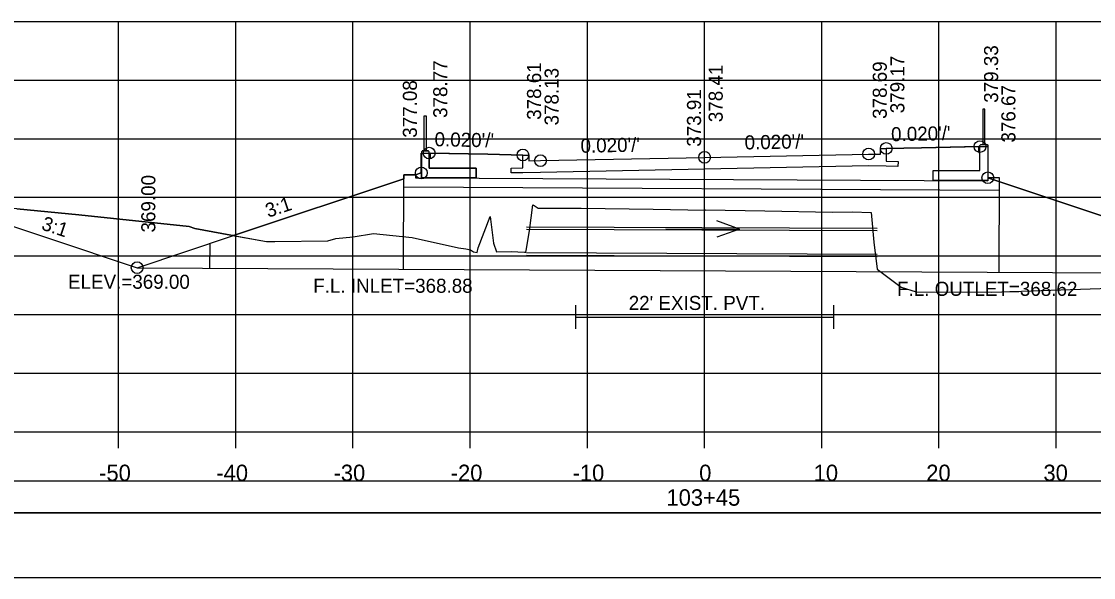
# Model space of a CAD drawing. Extents: x -37291014 to -37290680, y -936053 to -933067.
# Drawn here: x -37290901.4 to -37290809.9, y -935351.7 to -935304.3 of the extents above; entities that cross this region are included whole.
import ezdxf

# ---------------------------------------------------------------- set-up
doc = ezdxf.new("R2010")
doc.units = 0
for name, color, linetype in [('Default', 7, 'Continuous'), ('R_Alt Surface', 7, 'Continuous'), ('R_Axis', 7, 'Continuous'), ('R_Axis Annot', 7, 'Continuous'), ('R_Contours', 7, 'Continuous'), ('R_Exist Surface', 7, 'Continuous'), ('R_Fin Surface', 7, 'Continuous'), ('R_Grid', 7, 'Continuous'), ('R_No Plot', 7, 'Continuous'), ('R_Water', 7, 'Continuous'), ('R_Water Annot', 7, 'Continuous'), ('R_Xsect Elev', 7, 'Continuous'), ('R_Xsect Slope', 7, 'Continuous')]:
    doc.layers.add(name, color=color, linetype=linetype)

msp = doc.modelspace()

# ---------------------------------------------------------------- linework, layer by layer
at = {"layer": 'Default'}
for p, q in [((-37290867.018, -935315.353), (-37290867.018, -935312.353)), ((-37290867.018, -935312.353), (-37290866.852, -935312.353)), ((-37290866.852, -935312.353), (-37290866.852, -935315.353)), ((-37290819.352, -935311.793), (-37290819.352, -935314.793)), ((-37290819.185, -935311.793), (-37290819.352, -935311.793)), ((-37290819.185, -935314.793), (-37290819.185, -935311.793)), ((-37290819.602, -935314.876), (-37290819.539, -935314.814)), ((-37290819.602, -935317.034), (-37290819.602, -935314.876)), ((-37290819.539, -935314.793), (-37290818.997, -935314.793)), ((-37290819.539, -935314.814), (-37290819.539, -935314.793)), ((-37290819.539, -935314.814), (-37290818.997, -935314.814)), ((-37290818.997, -935314.793), (-37290818.997, -935314.814)), ((-37290818.997, -935314.814), (-37290818.935, -935314.876)), ((-37290818.935, -935314.876), (-37290818.935, -935317.868)), ((-37290867.206, -935315.374), (-37290867.268, -935315.436)), ((-37290867.268, -935315.436), (-37290867.268, -935317.643)), ((-37290866.664, -935315.353), (-37290867.206, -935315.353)), ((-37290867.206, -935315.353), (-37290867.206, -935315.374)), ((-37290866.664, -935315.374), (-37290867.206, -935315.374)), ((-37290866.664, -935315.374), (-37290866.664, -935315.353)), ((-37290866.602, -935315.436), (-37290866.664, -935315.374)), ((-37290866.602, -935316.81), (-37290866.602, -935315.436)), ((-37290862.598, -935316.81), (-37290866.602, -935316.81)), ((-37290862.598, -935317.643), (-37290862.598, -935316.81)), ((-37290862.598, -935317.643), (-37290867.268, -935317.643)), ((-37290823.605, -935317.868), (-37290823.605, -935317.034)), ((-37290823.605, -935317.034), (-37290819.602, -935317.034)), ((-37290823.605, -935317.868), (-37290818.935, -935317.868))]:
    msp.add_line(p, q, dxfattribs=at)
for points in [[(-37290819.685, -935315.48), (-37290819.602, -935315.48), (-37290819.602, -935314.98), (-37290819.685, -935314.98), (-37290819.685, -935315.48)], [(-37290866.518, -935316.04), (-37290866.602, -935316.04), (-37290866.602, -935315.54), (-37290866.518, -935315.54), (-37290866.518, -935316.04)]]:
    msp.add_lwpolyline(points, dxfattribs=at)
for points in [[(-37290992.481, -935346.216), (-37290693.722, -935346.216), (-37290693.722, -935343.51), (-37290992.481, -935343.51)], [(-37290992.481, -935351.738), (-37290693.722, -935351.738), (-37290693.722, -935346.216), (-37290992.481, -935346.216)]]:
    msp.add_lwpolyline(points, close=True, dxfattribs=at)
at = {"layer": 'R_Alt Surface'}
for points in [[(-37290827.602, -935315.14), (-37290827.602, -935316.233), (-37290826.592, -935316.254), (-37290826.602, -935316.67), (-37290827.602, -935316.65), (-37290829.102, -935316.62), (-37290843.102, -935316.9), (-37290857.102, -935317.18), (-37290858.602, -935317.21), (-37290859.602, -935317.23), (-37290859.612, -935316.814), (-37290858.602, -935316.793), (-37290858.602, -935315.7)], [(-37290854.102, -935328.517), (-37290854.102, -935330.517)], [(-37290832.102, -935328.517), (-37290832.102, -935330.517)], [(-37290854.102, -935329.517), (-37290832.102, -935329.517)]]:
    msp.add_lwpolyline(points, dxfattribs=at)
at = {"layer": 'R_Axis'}
for p, q in [((-37290993.102, -935339.31), (-37290693.102, -935339.31)), ((-37290893.102, -935340.71), (-37290893.102, -935339.31)), ((-37290883.102, -935340.71), (-37290883.102, -935339.31)), ((-37290873.102, -935340.71), (-37290873.102, -935339.31)), ((-37290863.102, -935340.71), (-37290863.102, -935339.31)), ((-37290853.102, -935340.71), (-37290853.102, -935339.31)), ((-37290843.102, -935340.71), (-37290843.102, -935339.31)), ((-37290833.102, -935340.71), (-37290833.102, -935339.31)), ((-37290823.102, -935340.71), (-37290823.102, -935339.31)), ((-37290813.102, -935340.71), (-37290813.102, -935339.31))]:
    msp.add_line(p, q, dxfattribs=at)
at = {"layer": 'R_Contours'}
for p, q in [((-37290819.602, -935317.034), (-37290819.602, -935315.48)), ((-37290866.602, -935316.04), (-37290866.602, -935316.81)), ((-37290866.602, -935316.81), (-37290862.598, -935316.81)), ((-37290862.598, -935316.81), (-37290862.598, -935317.643)), ((-37290867.268, -935317.643), (-37290867.268, -935317.23)), ((-37290862.598, -935317.643), (-37290867.268, -935317.643)), ((-37290823.605, -935317.868), (-37290823.605, -935317.034)), ((-37290823.605, -935317.034), (-37290819.602, -935317.034)), ((-37290818.935, -935317.64), (-37290818.935, -935317.868)), ((-37290818.935, -935317.868), (-37290823.605, -935317.868)), ((-37290883.304, -935322.573), (-37290883.537, -935322.531))]:
    msp.add_line(p, q, dxfattribs=at)
for points in [[(-37290819.685, -935314.982), (-37290824.602, -935315.08), (-37290827.602, -935315.14)], [(-37290819.602, -935315.48), (-37290819.685, -935315.48), (-37290819.685, -935314.982)], [(-37290866.518, -935315.542), (-37290866.518, -935316.04), (-37290866.602, -935316.04)], [(-37290858.602, -935315.7), (-37290861.602, -935315.64), (-37290866.518, -935315.542)], [(-37290827.602, -935315.14), (-37290827.602, -935316.233), (-37290826.592, -935316.254), (-37290826.602, -935316.67), (-37290827.602, -935316.65), (-37290829.102, -935316.62), (-37290843.102, -935316.9), (-37290857.102, -935317.18), (-37290858.602, -935317.21), (-37290859.602, -935317.23), (-37290859.612, -935316.814), (-37290858.602, -935316.793), (-37290858.602, -935315.7)], [(-37290867.273, -935317.23), (-37290867.762, -935317.393), (-37290868.762, -935317.385), (-37290868.763, -935317.727), (-37290883.304, -935322.573)], [(-37290867.268, -935317.23), (-37290867.273, -935317.23)], [(-37290818.931, -935317.64), (-37290818.935, -935317.64)], [(-37290792.881, -935326.322), (-37290795.774, -935325.358), (-37290818.931, -935317.64)], [(-37290883.537, -935322.531), (-37290886.603, -935321.977), (-37290887.068, -935321.808), (-37290896.495, -935320.808), (-37290901.786, -935320.281), (-37290906.76, -935320.229)], [(-37290906.76, -935320.229), (-37290891.515, -935325.31), (-37290883.304, -935322.573)], [(-37290883.304, -935322.573), (-37290880.471, -935323.085), (-37290879.756, -935323.065), (-37290875.249, -935323.015), (-37290874.553, -935322.828), (-37290873.089, -935322.671), (-37290871.345, -935322.391), (-37290868.054, -935322.737), (-37290864.09, -935323.608), (-37290863.469, -935323.712), (-37290863.063, -935323.792), (-37290862.824, -935323.961), (-37290862.505, -935324.025), (-37290862.424, -935323.631), (-37290861.394, -935320.942), (-37290861.097, -935323.212), (-37290860.858, -935323.964), (-37290859.59, -935323.925), (-37290858.466, -935323.982), (-37290858.346, -935323.986), (-37290858.328, -935323.836), (-37290858.045, -935322.171), (-37290857.763, -935319.937), (-37290857.65, -935320.015), (-37290857.302, -935320.24), (-37290856.619, -935320.246), (-37290853.626, -935320.229), (-37290847.481, -935320.323), (-37290843.054, -935320.401), (-37290843.023, -935320.385), (-37290837.955, -935320.461), (-37290832.174, -935320.572), (-37290830.517, -935320.553), (-37290828.897, -935320.598), (-37290828.662, -935323.123), (-37290828.379, -935325.431), (-37290826.325, -935326.98), (-37290825.034, -935327.371), (-37290818.601, -935327.388), (-37290805.994, -935326.984)]]:
    msp.add_lwpolyline(points, dxfattribs=at)
at = {"layer": 'R_Exist Surface'}
msp.add_lwpolyline([(-37290901.786, -935320.281), (-37290896.495, -935320.808), (-37290887.068, -935321.808), (-37290886.603, -935321.977), (-37290883.537, -935322.531), (-37290880.471, -935323.085), (-37290879.756, -935323.065), (-37290875.249, -935323.015), (-37290874.553, -935322.828), (-37290873.089, -935322.671), (-37290871.345, -935322.391), (-37290868.054, -935322.737), (-37290864.09, -935323.608), (-37290863.469, -935323.712), (-37290863.063, -935323.792), (-37290862.824, -935323.961), (-37290862.505, -935324.025), (-37290862.424, -935323.631), (-37290861.394, -935320.942), (-37290861.097, -935323.212), (-37290860.858, -935323.964), (-37290859.59, -935323.925), (-37290858.466, -935323.982), (-37290858.346, -935323.986), (-37290858.328, -935323.836), (-37290858.045, -935322.171), (-37290857.763, -935319.937), (-37290857.65, -935320.015), (-37290857.302, -935320.24), (-37290856.619, -935320.246), (-37290853.626, -935320.229), (-37290847.481, -935320.323), (-37290843.054, -935320.401), (-37290843.023, -935320.385), (-37290837.955, -935320.461), (-37290832.174, -935320.572), (-37290830.517, -935320.553), (-37290828.897, -935320.598), (-37290828.662, -935323.123), (-37290828.379, -935325.431), (-37290826.325, -935326.98), (-37290825.034, -935327.371), (-37290818.601, -935327.388), (-37290805.994, -935326.984)], dxfattribs=at)
at = {"layer": 'R_Fin Surface'}
msp.add_lwpolyline([(-37290906.76, -935320.229), (-37290891.515, -935325.31), (-37290883.304, -935322.573), (-37290868.763, -935317.727), (-37290868.762, -935317.385), (-37290867.762, -935317.393), (-37290867.273, -935317.23), (-37290867.272, -935315.54), (-37290866.602, -935315.54), (-37290861.602, -935315.64), (-37290858.602, -935315.7), (-37290858.102, -935315.7), (-37290858.101, -935316.2), (-37290857.102, -935316.18), (-37290843.102, -935315.9), (-37290829.102, -935315.62), (-37290828.103, -935315.64), (-37290828.102, -935315.14), (-37290827.602, -935315.14), (-37290824.602, -935315.08), (-37290819.602, -935314.98), (-37290818.932, -935314.98), (-37290818.931, -935317.64), (-37290795.774, -935325.358)], dxfattribs=at)
at = {"layer": 'R_Grid'}
for p, q in [((-37290993.102, -935304.31), (-37290693.102, -935304.31)), ((-37290893.102, -935339.31), (-37290893.102, -935304.31)), ((-37290883.102, -935339.31), (-37290883.102, -935304.31)), ((-37290873.102, -935339.31), (-37290873.102, -935304.31)), ((-37290863.102, -935339.31), (-37290863.102, -935304.31)), ((-37290853.102, -935339.31), (-37290853.102, -935304.31)), ((-37290843.102, -935339.31), (-37290843.102, -935304.31)), ((-37290833.102, -935339.31), (-37290833.102, -935304.31)), ((-37290823.102, -935339.31), (-37290823.102, -935304.31)), ((-37290813.102, -935339.31), (-37290813.102, -935304.31)), ((-37290993.102, -935309.31), (-37290693.102, -935309.31)), ((-37290993.102, -935314.31), (-37290693.102, -935314.31)), ((-37290993.102, -935319.31), (-37290693.102, -935319.31)), ((-37290993.102, -935324.31), (-37290693.102, -935324.31)), ((-37290993.102, -935329.31), (-37290693.102, -935329.31)), ((-37290993.102, -935334.31), (-37290693.102, -935334.31)), ((-37290993.102, -935339.31), (-37290693.102, -935339.31))]:
    msp.add_line(p, q, dxfattribs=at)
at = {"layer": 'R_No Plot'}
for p, q in [((-37290858.295, -935321.813), (-37290828.372, -935321.935)), ((-37290858.295, -935324.23), (-37290828.372, -935324.352))]:
    msp.add_line(p, q, dxfattribs=at)
for centre in [(-37290866.602, -935315.54), (-37290827.602, -935315.14), (-37290819.602, -935314.98), (-37290858.602, -935315.7), (-37290857.102, -935316.18), (-37290843.102, -935315.9), (-37290829.102, -935315.62), (-37290829.102, -935315.62), (-37290867.273, -935317.23), (-37290818.931, -935317.64), (-37290891.515, -935325.31)]:
    msp.add_circle(centre, 0.5, dxfattribs=at)
at = {"layer": 'R_Water'}
for p, q in [((-37290868.803, -935325.427), (-37290868.762, -935317.385)), ((-37290868.762, -935317.385), (-37290867.762, -935317.39)), ((-37290867.762, -935317.39), (-37290867.763, -935317.64)), ((-37290867.763, -935317.64), (-37290818.932, -935317.892)), ((-37290818.93, -935317.642), (-37290818.932, -935317.892)), ((-37290817.93, -935317.647), (-37290818.93, -935317.642)), ((-37290817.972, -935325.688), (-37290817.93, -935317.647)), ((-37290868.767, -935318.427), (-37290817.936, -935318.689)), ((-37290858.295, -935322.022), (-37290828.372, -935322.144)), ((-37290885.303, -935325.342), (-37290885.292, -935323.234)), ((-37290858.295, -935324.022), (-37290828.372, -935324.144)), ((-37290891.525, -935325.31), (-37290794.412, -935325.81))]:
    msp.add_line(p, q, dxfattribs=at)
at = {"layer": 'R_Water Annot'}
for p, q in [((-37290840.125, -935322.026), (-37290842.046, -935321.318)), ((-37290846.41, -935322.001), (-37290840.125, -935322.026)), ((-37290840.125, -935322.026), (-37290842.051, -935322.719))]:
    msp.add_line(p, q, dxfattribs=at)
at = {"layer": 'R_Xsect Elev'}
msp.add_line((-37290843.102, -935320.4), (-37290843.102, -935307.995), dxfattribs=at)

# ---------------------------------------------------------------- texts
at = {"layer": 'R_Axis Annot'}
for s, p in [('-50', (-37290894.761, -935343.51)), ('-40', (-37290884.761, -935343.51)), ('-30', (-37290874.761, -935343.51)), ('-20', (-37290864.761, -935343.51)), ('-10', (-37290854.364, -935343.51)), ('0', (-37290843.559, -935343.51)), ('10', (-37290833.791, -935343.51)), ('20', (-37290824.187, -935343.51)), ('30', (-37290814.187, -935343.51)), ('103+45', (-37290846.354, -935345.61))]:
    msp.add_text(s, height=1.4, dxfattribs=at).set_placement(p)
at = {"layer": 'R_Water'}
msp.add_text("22' EXIST. PVT.", height=1.2, dxfattribs=at).set_placement((-37290849.575, -935328.917))
at = {"layer": 'R_Water Annot'}
for s, p in [('F.L. INLET=368.88', (-37290876.494, -935327.451)), ('F.L. OUTLET=368.62', (-37290826.674, -935327.713))]:
    msp.add_text(s, height=1.2, dxfattribs=at).set_placement(p)
at = {"layer": 'R_Xsect Elev'}
for s, p in [('379.33', (-37290818.052, -935311.246)), ('378.77', (-37290865.052, -935312.54)), ('379.17', (-37290826.052, -935312.14)), ('378.61', (-37290857.052, -935312.7)), ('378.13', (-37290855.552, -935313.18)), ('378.41', (-37290841.552, -935312.9)), ('378.69', (-37290827.552, -935312.62)), ('377.08', (-37290867.646, -935314.23)), ('373.91', (-37290843.402, -935314.995)), ('376.67', (-37290816.578, -935314.64)), ('369.00', (-37290889.965, -935322.31))]:
    msp.add_text(s, height=1.2, rotation=90, dxfattribs=at).set_placement(p)
msp.add_text('ELEV.=369.00', height=1.2, dxfattribs=at).set_placement((-37290897.416, -935327.11))
at = {"layer": 'R_Xsect Slope'}
for s, rotation, p in [("0.020'/'", 1.14576, (-37290827.175, -935314.532)), ("0.020'/'", 358.85424, (-37290866.151, -935314.949)), ("0.020'/'", 1.14576, (-37290853.675, -935315.512)), ("0.020'/'", 1.14576, (-37290839.675, -935315.232)), ('3:1', 18.43323, (-37290880.341, -935321.058)), ('3:1', 341.56677, (-37290899.768, -935322.032))]:
    msp.add_text(s, height=1.2, rotation=rotation, dxfattribs=at).set_placement(p)

doc.saveas('drawing.dxf')
